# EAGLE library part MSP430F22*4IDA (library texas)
MIXED SIGNAL MICROCONTROLLER Source: http://focus.ti.com/lit/ds/symlink/msp430f2274.pdf
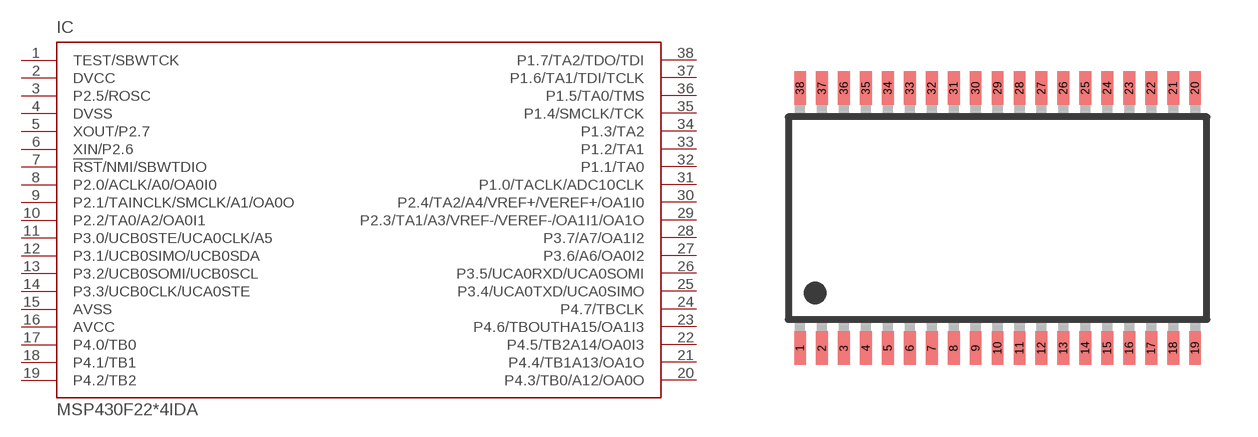
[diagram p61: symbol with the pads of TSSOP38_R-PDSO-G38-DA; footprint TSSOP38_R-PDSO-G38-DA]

Designator prefix IC

## MSP430F2234IDA (MPN: MSP430F2234IDA; OC_FARNELL: 1649419; OC_NEWARK: 28M6320), MSP430F2254IDA (MPN: MSP430F2254IDA; OC_FARNELL: 1649422; OC_NEWARK: 28M6334), MSP430F2274IDA (MPN: MSP430F2274IDA; OC_FARNELL: 1610179; OC_NEWARK: 28M6350)  [TSSOP38_R-PDSO-G38-DA]
1  TEST/SBWTCK  in
2  DVCC  pwr
3  P2.5/ROSC
4  DVSS  pwr
5  XOUT/P2.7
6  XIN/P2.6
7  !RST!/NMI/SBWTDIO  in
8  P2.0/ACLK/A0/OA0I0
9  P2.1/TAINCLK/SMCLK/A1/OA0O
10  P2.2/TA0/A2/OA0I1
11  P3.0/UCB0STE/UCA0CLK/A5
12  P3.1/UCB0SIMO/UCB0SDA
13  P3.2/UCB0SOMI/UCB0SCL
14  P3.3/UCB0CLK/UCA0STE
15  AVSS  pwr
16  AVCC  pwr
17  P4.0/TB0
18  P4.1/TB1
19  P4.2/TB2
20  P4.3/TB0/A12/OA0O
21  P4.4/TB1A13/OA1O
22  P4.5/TB2A14/OA0I3
23  P4.6/TBOUTHA15/OA1I3
24  P4.7/TBCLK
25  P3.4/UCA0TXD/UCA0SIMO
26  P3.5/UCA0RXD/UCA0SOMI
27  P3.6/A6/OA0I2
28  P3.7/A7/OA1I2
29  P2.3/TA1/A3/VREF-/VEREF-/OA1I1/OA1O
30  P2.4/TA2/A4/VREF+/VEREF+/OA1I0
31  P1.0/TACLK/ADC10CLK
32  P1.1/TA0
33  P1.2/TA1
34  P1.3/TA2
35  P1.4/SMCLK/TCK
36  P1.5/TA0/TMS
37  P1.6/TA1/TDI/TCLK
38  P1.7/TA2/TDO/TDI

## Footprint TSSOP38_R-PDSO-G38-DA (pad centres in mm)
TSSOP 38 DA (R-PDSO-G38) Auto generated by make-symbol-device-package-bsdl.ulp Rev. 28 Source: http://focus.ti.com/lit/ds/symlink/msp430f2274.pdf
smd 0.35 x 1: 1 -5.85,-3.85; 2 -5.2,-3.85; 3 -4.55,-3.85; 4 -3.9,-3.85; 5 -3.25,-3.85; 6 -2.6,-3.85; 7 -1.95,-3.85; 8 -1.3,-3.85; 9 -0.65,-3.85; 10 0,-3.85; 11 0.65,-3.85; 12 1.3,-3.85; 13 1.95,-3.85; 14 2.6,-3.85; 15 3.25,-3.85; 16 3.9,-3.85; 17 4.55,-3.85; 18 5.2,-3.85; 19 5.85,-3.85; 20 5.85,3.85; 21 5.2,3.85; 22 4.55,3.85; 23 3.9,3.85; 24 3.25,3.85; 25 2.6,3.85; 26 1.95,3.85; 27 1.3,3.85; 28 0.65,3.85; 29 0,3.85; 30 -0.65,3.85; 31 -1.3,3.85; 32 -1.95,3.85; 33 -2.6,3.85; 34 -3.25,3.85; 35 -3.9,3.85; 36 -4.55,3.85; 37 -5.2,3.85; 38 -5.85,3.85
